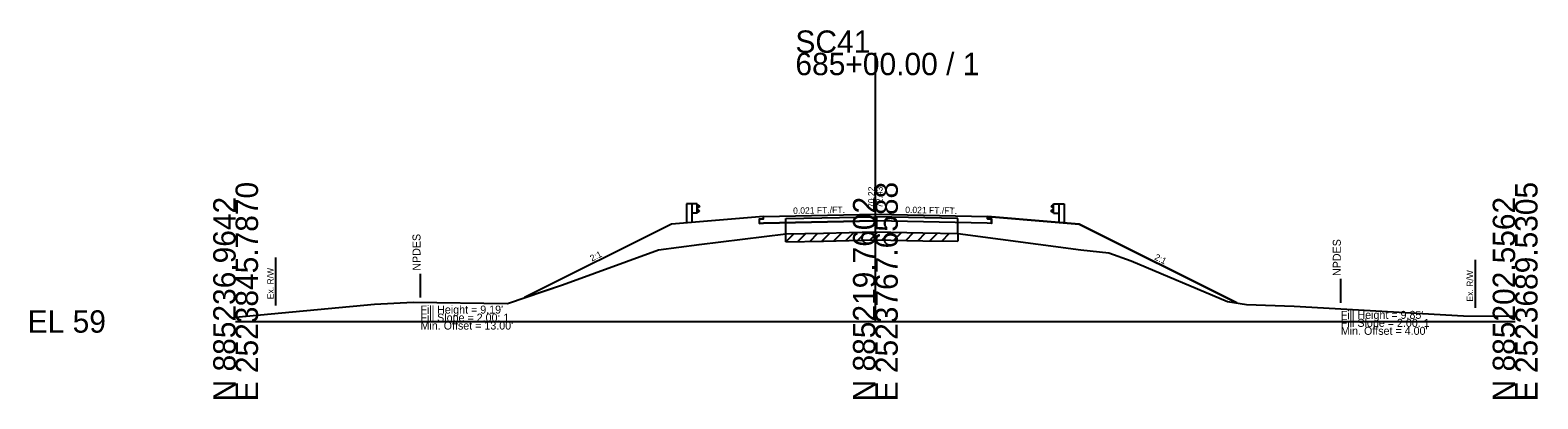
# Model space of a CAD drawing. Extents: x -26 to 183, y -10 to 24021.
# Drawn here: x -25.7 to 162.8, y 14490.3 to 14536.5 of the extents above; entities that cross this region are included whole.
import ezdxf

# ---------------------------------------------------------------- set-up
doc = ezdxf.new("R2010")
doc.units = 0
for name, color, linetype in [('RD_GPK_XS_Cell', 7, 'Continuous'), ('RD_XS_Base', 7, 'Continuous'), ('RD_XS_Buildup', 7, 'Continuous'), ('RD_XS_EarthShd', 7, 'Continuous'), ('RD_XS_EwShp', 7, 'Continuous'), ('RD_XS_ExGround', 7, 'Continuous'), ('RD_XS_ExPaveRet', 7, 'Continuous'), ('RD_XS_ExRW', 7, 'Continuous'), ('RD_XS_GR', 7, 'Continuous'), ('RD_XS_NPDES', 7, 'Continuous'), ('RD_XS_Pave', 7, 'Continuous'), ('RD_XS_TieSlope', 7, 'Continuous'), ('RD_XS_TX_Elev_EX', 7, 'Continuous'), ('RD_XS_TX_Elev_PR', 7, 'Continuous'), ('RD_XS_TX_Slope', 7, 'Continuous'), ('RD_XS_TX_Warning', 7, 'Continuous')]:
    doc.layers.add(name, color=color, linetype=linetype)

msp = doc.modelspace()

# ---------------------------------------------------------------- linework, layer by layer
at = {"layer": 'RD_GPK_XS_Cell'}
for p, q in [((80, 14500), (80, 14533.65)), ((0, 14500), (80, 14500)), ((80, 14500), (160, 14500))]:
    msp.add_line(p, q, dxfattribs=at)
at = {"layer": 'RD_XS_Base'}
for p in [(66.01, 14512.3), (93.99, 14512.3)]:
    msp.add_line(p, (80, 14512.59), dxfattribs=at)
at = {"layer": 'RD_XS_Buildup'}
for p, q in [((68.8, 14512.88), (80, 14513.11)), ((68.8, 14510.97), (68.8, 14512.88)), ((90.33, 14512.89), (80, 14513.11)), ((90.33, 14511.04), (90.33, 14512.89))]:
    msp.add_line(p, q, dxfattribs=at)
at = {"layer": 'RD_XS_EarthShd'}
for p, q in [((58, 14512.47), (54.5, 14512.18)), ((66, 14513.14), (58, 14512.47)), ((94, 14513.14), (102, 14512.47)), ((102, 14512.47), (105.5, 14512.18))]:
    msp.add_line(p, q, dxfattribs=at)
at = {"layer": 'RD_XS_EwShp'}
msp.add_lwpolyline([(36.12, 14502.99), (40.87, 14504.6), (52.88, 14508.97), (57.95, 14509.64), (68.8, 14510.97), (73.53, 14511.06), (79.94, 14511.22), (85.94, 14511.1), (90.33, 14511.04), (105.69, 14508.98), (109.21, 14508.6), (112, 14507.59), (124.05, 14502.51), (125.2, 14502.33), (105.5, 14512.18), (102, 14512.47), (94, 14513.14), (94, 14512.85), (94.5, 14512.84), (94.5, 14512.29), (93.99, 14512.3), (80, 14512.59), (66.01, 14512.3), (65.5, 14512.29), (65.5, 14512.84), (66, 14512.85), (66, 14513.14), (58, 14512.47), (54.5, 14512.18)], close=True, dxfattribs=at)
msp.add_lwpolyline([(36.12, 14502.99), (40.87, 14504.6), (52.88, 14508.97), (57.95, 14509.64), (68.8, 14510.97), (73.53, 14511.06), (79.94, 14511.22), (85.94, 14511.1), (90.33, 14511.04), (105.69, 14508.98), (109.21, 14508.6), (112, 14507.59), (124.05, 14502.51), (125.2, 14502.33), (105.5, 14512.18), (102, 14512.47), (94, 14513.14), (94, 14512.85), (94.5, 14512.84), (94.5, 14512.29), (93.99, 14512.3), (80, 14512.59), (66.01, 14512.3), (65.5, 14512.29), (65.5, 14512.84), (66, 14512.85), (66, 14513.14), (58, 14512.47), (54.5, 14512.18)], close=True, dxfattribs=at)
msp.add_lwpolyline([(36.12, 14502.99), (40.87, 14504.6), (52.88, 14508.97), (57.95, 14509.64), (68.8, 14510.97), (73.53, 14511.06), (79.94, 14511.22), (85.94, 14511.1), (90.33, 14511.04), (105.69, 14508.98), (109.21, 14508.6), (112, 14507.59), (124.05, 14502.51), (125.2, 14502.33), (105.5, 14512.18), (102, 14512.47), (94, 14513.14), (94, 14512.85), (94.5, 14512.84), (94.5, 14512.29), (93.99, 14512.3), (80, 14512.59), (66.01, 14512.3), (65.5, 14512.29), (65.5, 14512.84), (66, 14512.85), (66, 14513.14), (58, 14512.47), (54.5, 14512.18)], close=True, dxfattribs=at)
msp.add_lwpolyline([(36.12, 14502.99), (40.87, 14504.6), (52.88, 14508.97), (57.95, 14509.64), (68.8, 14510.97), (73.53, 14511.06), (79.94, 14511.22), (85.94, 14511.1), (90.33, 14511.04), (105.69, 14508.98), (109.21, 14508.6), (112, 14507.59), (124.05, 14502.51), (125.2, 14502.33), (105.5, 14512.18), (102, 14512.47), (94, 14513.14), (94, 14512.85), (94.5, 14512.84), (94.5, 14512.29), (93.99, 14512.3), (80, 14512.59), (66.01, 14512.3), (65.5, 14512.29), (65.5, 14512.84), (66, 14512.85), (66, 14513.14), (58, 14512.47), (54.5, 14512.18)], close=True, dxfattribs=at)
at = {"layer": 'RD_XS_ExGround'}
for p, q in [((52.88, 14508.97), (57.95, 14509.64)), ((57.95, 14509.64), (68.8, 14510.97)), ((68.8, 14510.97), (73.53, 14511.06)), ((73.53, 14511.06), (79.94, 14511.22)), ((79.94, 14511.22), (85.94, 14511.1)), ((85.94, 14511.1), (90.33, 14511.04)), ((90.33, 14511.04), (105.69, 14508.98)), ((40.87, 14504.6), (52.88, 14508.97)), ((105.69, 14508.98), (109.21, 14508.6)), ((109.21, 14508.6), (112, 14507.59)), ((112, 14507.59), (124.05, 14502.51)), ((33.98, 14502.26), (40.87, 14504.6)), ((0, 14500.53), (17.36, 14502.17)), ((17.36, 14502.17), (22.19, 14502.42)), ((22.19, 14502.42), (33.98, 14502.26)), ((124.05, 14502.51), (126.41, 14502.14)), ((126.41, 14502.14), (132.36, 14501.94)), ((132.36, 14501.94), (153.56, 14500.73)), ((153.56, 14500.73), (160, 14500.67))]:
    msp.add_line(p, q, dxfattribs=at)
at = {"layer": 'RD_XS_ExPaveRet'}
for p, q in [((68.8, 14509.97), (69.82, 14510.99)), ((68.8, 14509.97), (68.8, 14510.97)), ((68.8, 14509.97), (73.53, 14510.06)), ((70.3, 14510), (71.32, 14511.02)), ((71.8, 14510.03), (72.82, 14511.05)), ((73.3, 14510.06), (74.32, 14511.08)), ((73.53, 14510.06), (79.94, 14510.22)), ((74.8, 14510.09), (75.82, 14511.12)), ((76.3, 14510.13), (77.32, 14511.15)), ((77.8, 14510.17), (78.82, 14511.19)), ((79.3, 14510.2), (80.31, 14511.21)), ((79.94, 14510.22), (85.94, 14510.1)), ((80.8, 14510.2), (81.78, 14511.18)), ((82.3, 14510.17), (83.28, 14511.15)), ((83.8, 14510.14), (84.78, 14511.13)), ((85.3, 14510.12), (86.28, 14511.1)), ((85.94, 14510.1), (90.33, 14510.04)), ((86.8, 14510.09), (87.78, 14511.08)), ((88.3, 14510.07), (89.28, 14511.05)), ((90.33, 14511.04), (90.33, 14510.04))]:
    msp.add_line(p, q, dxfattribs=at)
at = {"layer": 'RD_XS_ExRW'}
for p, q in [((5, 14508), (5, 14502)), ((155, 14507.72), (155, 14501.72))]:
    msp.add_line(p, q, dxfattribs=at)
at = {"layer": 'RD_XS_GR'}
for p, q in [((56.4, 14514.72), (56.4, 14512.34)), ((57.06, 14514.72), (56.4, 14514.72)), ((57.06, 14514.72), (57.06, 14512.39)), ((57.73, 14514.72), (57.06, 14514.72)), ((57.73, 14513.55), (57.06, 14513.55)), ((57.73, 14513.55), (57.73, 14514.72)), ((57.73, 14514.65), (58, 14514.45)), ((58, 14514.4), (57.73, 14514.2)), ((58, 14513.88), (57.73, 14514.08)), ((57.73, 14513.63), (58, 14513.83)), ((58, 14514.45), (58, 14514.4)), ((58, 14513.83), (58, 14513.88)), ((102.27, 14514.65), (102, 14514.45)), ((102, 14514.45), (102, 14514.4)), ((102, 14514.4), (102.27, 14514.2)), ((102, 14513.88), (102.27, 14514.08)), ((102, 14513.83), (102, 14513.88)), ((102.27, 14513.63), (102, 14513.83)), ((102.27, 14513.55), (102.27, 14514.72)), ((102.27, 14514.72), (102.94, 14514.72)), ((102.27, 14513.55), (102.94, 14513.55)), ((102.94, 14514.72), (102.94, 14512.39)), ((102.94, 14514.72), (103.6, 14514.72)), ((103.6, 14514.72), (103.6, 14512.34))]:
    msp.add_line(p, q, dxfattribs=at)
at = {"layer": 'RD_XS_NPDES'}
for p, q in [((23.12, 14502.99), (23.12, 14505.99)), ((138.2, 14502.33), (138.2, 14505.33))]:
    msp.add_line(p, q, dxfattribs=at)
at = {"layer": 'RD_XS_Pave'}
for p, q in [((66, 14513.14), (80, 14513.43)), ((80, 14513.43), (94, 14513.14)), ((65.5, 14512.84), (66, 14512.85)), ((65.5, 14512.29), (65.5, 14512.84)), ((65.5, 14512.29), (66.01, 14512.3)), ((66, 14512.85), (66, 14513.14)), ((94.5, 14512.29), (93.99, 14512.3)), ((94, 14512.85), (94, 14513.14)), ((94.5, 14512.84), (94, 14512.85)), ((94.5, 14512.29), (94.5, 14512.84))]:
    msp.add_line(p, q, dxfattribs=at)
at = {"layer": 'RD_XS_TieSlope'}
for p, q in [((54.5, 14512.18), (36.12, 14502.99)), ((105.5, 14512.18), (125.2, 14502.33))]:
    msp.add_line(p, q, dxfattribs=at)

# ---------------------------------------------------------------- texts
at = {"layer": 'RD_GPK_XS_Cell'}
for s, p in [('SC41', (70, 14533.65)), ('685+00.00 / 1', (70, 14530.85)), ('EL 59', (-26, 14498.6))]:
    msp.add_text(s, height=2.8, dxfattribs=at).set_placement(p)
for s, p in [('E 2523845.7870', (2.8, 14490)), ('E 2523767.6588', (82.8, 14490)), ('E 2523689.5305', (162.8, 14490)), ('N 885236.9642', (0, 14490)), ('N 885219.7602', (80, 14490)), ('N 885202.5562', (160, 14490))]:
    msp.add_text(s, height=2.8, rotation=90, dxfattribs=at).set_placement(p)
at = {"layer": 'RD_XS_ExRW'}
for p in [(4.75, 14502.79), (154.75, 14502.5)]:
    msp.add_text('Ex. R/W ', height=0.8, rotation=90, dxfattribs=at).set_placement(p)
at = {"layer": 'RD_XS_TX_Elev_EX'}
msp.add_text('70.22', height=0.8, rotation=90, dxfattribs=at).set_placement((79.9, 14514.22))
at = {"layer": 'RD_XS_TX_Elev_PR'}
msp.add_text('72.43', height=0.8, rotation=90, dxfattribs=at).set_placement((80.9, 14514.22))
at = {"layer": 'RD_XS_TX_Slope'}
for s, rotation, p in [('0.021 FT./FT.', 1.1916, (69.72, 14513.47)), ('0.021 FT./FT.', 358.8084, (83.73, 14513.6)), ('2:1', 26.5651, (44.56, 14507.49)), ('2:1', 333.4349, (114.82, 14507.8))]:
    msp.add_text(s, height=0.8, rotation=rotation, dxfattribs=at).set_placement(p)
at = {"layer": 'RD_XS_TX_Warning'}
for p in [(23.12, 14505.99), (138.2, 14505.33)]:
    msp.add_text(' NPDES', height=1, rotation=90, dxfattribs=at).set_placement(p)
for s, p in [("Fill Height = 9.19' ", (23.12, 14500.99)), ('Fill Slope = 2.00: 1', (23.12, 14499.99)), ("Min. Offset = 13.00' ", (23.12, 14498.99)), ("Fill Height = 9.85' ", (138.2, 14500.33)), ('Fill Slope = 2.00: 1', (138.2, 14499.33)), ("Min. Offset = 4.00' ", (138.2, 14498.33))]:
    msp.add_text(s, height=1, dxfattribs=at).set_placement(p)

doc.saveas('drawing.dxf')
